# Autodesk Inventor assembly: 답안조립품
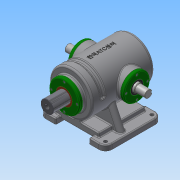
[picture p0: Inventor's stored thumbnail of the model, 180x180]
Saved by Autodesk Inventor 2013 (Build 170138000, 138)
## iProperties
Created: 2018-07
Part Number: 답안조립품
Document SubType Name: Assembly
Designer: Administrator
Mass: 8560.47 g
Surface Area: 4294.68 cm^2
Volume: 2307.06 cm^3
Density: 3.71055 g/cm^3
Author: Administrator
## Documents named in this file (13)
- C:\Users\Administrator\Desktop\380628V1002\380628V1002\답안조립품.iam
- C:\Users\Administrator\Desktop\380628V1002\380628V1002\본체.ipt
- C:\Users\Administrator\Desktop\380628V1002\380628V1002\가변스프링.ipt
- C:\Users\Administrator\Desktop\380628V1002\380628V1002\베어링 6205.ipt
- 베어링 6205.ipt
- C:\Users\Administrator\Desktop\380628V1002\380628V1002\볼트 M4.ipt
- C:\Users\Administrator\Desktop\380628V1002\380628V1002\부시.ipt
- C:\Users\Administrator\Desktop\380628V1002\380628V1002\슬라이드 커버.ipt
- C:\Users\Administrator\Desktop\380628V1002\380628V1002\슬라이드.ipt
- C:\Users\Administrator\Desktop\380628V1002\380628V1002\오일실.ipt
- 오일실.ipt
- C:\Users\Administrator\Desktop\380628V1002\380628V1002\축 커버.ipt
- C:\Users\Administrator\Desktop\380628V1002\380628V1002\편심축.ipt
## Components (1 placed, 1 different names)
1. 가변스프링:1
